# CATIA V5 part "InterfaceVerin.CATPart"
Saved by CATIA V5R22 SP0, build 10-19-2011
Part number: InterfaceVerin
Material "Vert": density 7860 kg/m3, Young's modulus 2e+11 Pa, Poisson ratio 0.266
Bounding box of the stored display mesh (mm): x 0 to 114.936, y -17 to 72, z 0 to 43
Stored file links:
  Z:\S9A\PER\CAO_Projet_ZG4\Cadre\Chariot_Y\Prehenseur\InterfaceVerin.CATPart
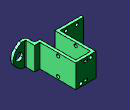
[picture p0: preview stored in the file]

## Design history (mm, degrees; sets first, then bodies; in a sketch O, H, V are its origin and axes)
Body1 (main body), material "Vert"
  Sketch1 on xy-plane, origin (0, 0, 0), H (1, 0, 0), V (0, 1, 0)
    line L1 (0, 0) -> (49, 0)
    line L2 (87, 0) -> (87, -11)
    point P1 (87, -17)
    line L3 (93, -17) -> (117, -17)
    point P2 (117, -17)
    point P3 (87, 0)
    point P4 (87, 0)
    arc A1 centre (93, -11) radius 6 from (93, -17) to (87, -11) cw
    line L4 (49, 0) -> (49, 67)
    line L5 (49, 67) -> (77, 67)
    line L6 (77, 67) -> (77, 0)
    line L7 (77, 0) -> (87, 0)
    distance P1 P2 = 30
    radius A1 = 6
    length L6 = 67
    length L5 = 28
    length L7 = 10
    length L2 = 11
    length L1 = 49
    horizontal: L1 H, L3 H, L5 H, L7 H
    vertical: L2 V, L4 V, L6 V
    coincidence: L3 P1, L2 P1, P4 P3, L1 L7
    tangency: A1 L3, A1 L2
  Pad1: profile Sketch1, direction (0, 0, 1), length 43, thin wall 5
  Sketch2 on face of Pad1, origin (98.7676, -12, 26.3573), H (1, 0, 0), V (0, 0, -1)
    point P1 (4.7324, 4.8573)
    reference projected line E1 (-5.7676, 26.3573) -> (18.2324, 26.3573) from edge [face of Pad1 | start face of Pad1]
    reference projected line E2 through (-5.7676, 0) direction (0, -1) from axis of face of Pad1
    distance P1 E1 = 21.5
    distance P1 E2 = 10.5
  Hole1: placed by Sketch2, at (103.5, -12, 21.5) direction (0, -1, 0), diameter 14, depth 21
  Sketch3 on face of Pad1, origin (0, 72, 0), H (-1, 0, 0), V (0, 0, 1)
    circle A1 centre (-72, 5) radius 3
    point P1 (-72, 5)
    circle A2 centre (-54, 38) radius 3
    point P2 (-54, 38)
    reference projected line E1 (-82, 0) -> (-44, 0) from edge [start face of Pad1 | face of Pad1]
    reference projected line E2 (-82, 43) -> (-44, 43) from edge [face of Pad1 | end face of Pad1]
    reference projected line E3 (-44, 0) -> (-44, 43) from edge [face of Pad1 | face of Pad1]
    line L1 (-66, 8) -> (-60, 8)
    line L2 (-60, 8) -> (-60, 4)
    line L3 (-60, 4) -> (-66, 4)
    line L4 (-66, 4) -> (-66, 8)
    line L5 (-66, 39) -> (-60, 39)
    line L6 (-60, 39) -> (-60, 35)
    line L7 (-60, 35) -> (-66, 35)
    line L8 (-66, 35) -> (-66, 39)
    reference projected line E4 (-82, 0) -> (-82, 43) from edge [face of Pad1 | face of Pad1]
    reference projected line E5 (-44, 0) -> (-44, 43) from edge [face of Pad1 | face of Pad1]
    reference projected line E6 (-82, 0) -> (-82, 43) from edge [face of Pad1 | face of Pad1]
    reference projected line E7 (-44, 0) -> (-44, 43) from edge [face of Pad1 | face of Pad1]
    reference projected line E8 (-82, 0) -> (-82, 43) from edge [face of Pad1 | face of Pad1]
    reference projected line E9 (-82, 43) -> (-44, 43) from edge [face of Pad1 | end face of Pad1]
    reference projected line E10 (-82, 0) -> (-44, 0) from edge [start face of Pad1 | face of Pad1]
    reference projected line E11 (-82, 0) -> (-82, 43) from edge [face of Pad1 | face of Pad1]
    reference projected line E12 (-82, 0) -> (-82, 43) from edge [face of Pad1 | face of Pad1]
    radius A2 = 3
    radius A1 = 3
    distance P1 E1 = 5
    distance P2 E2 = 5
    distance P2 E3 = 10
    length L5 = 6
    length L6 = 4
    length L3 = 6
    length L2 = 4
    distance L8 E4 = 16
    distance E5 E6 = 38 (reference)
    distance E7 E8 = 38 (reference)
    distance L5 E9 = 4
    distance L3 E10 = 4
    distance L4 E11 = 16
    distance P1 E12 = 10
    horizontal: L1 H, L3 H, L5 H, L7 H
    vertical: L2 V, L4 V, L6 V, L8 V
  Pocket1: profile Sketch3, direction (0, -1, 0), through (limit type 3)
  Sketch4 on face of Pad1, origin (0, 5, 0), H (-1, 0, 0), V (0, 0, 1)
    circle A1 centre (-33, 37) radius 3
    point P1 (-33, 37)
    circle A2 centre (-13, 37) radius 3
    point P2 (-13, 37)
    circle A3 centre (-33, 7) radius 3
    point P3 (-33, 7)
    circle A4 centre (-13, 7) radius 3
    point P4 (-13, 7)
    reference projected line E1 (0, 0) -> (-44, 0) from edge [face of Pad1 | start face of Pad1]
    reference projected line E2 (0, 43) -> (-44, 43) from edge [end face of Pad1 | face of Pad1]
    reference projected line E3 (0, 0) -> (-44, 0) from edge [face of Pad1 | start face of Pad1]
    reference projected line E4 (0, 0) -> (-44, 0) from edge [face of Pad1 | start face of Pad1]
    reference projected line E5 (-44, 0) -> (-44, 43) from edge [face of Pad1 | face of Pad1]
    reference projected line E6 (-44, 0) -> (-44, 43) from edge [face of Pad1 | face of Pad1]
    radius A1 = 3
    radius A2 = 3
    radius A3 = 3
    radius A4 = 3
    distance P2 P4 = 30
    distance P3 P1 = 30
    distance P3 E1 = 7
    distance E2 E3 = 43 (reference)
    distance P2 P1 = 20
    distance P4 P3 = 20
    distance P4 E4 = 7
    distance P3 E5 = 11
    distance P1 E6 = 11
  Pocket2: profile Sketch4, direction (0, -1, 0), through (limit type 3)
  Sketch5 on face of Pad1, origin (0, -12, 0), H (-1, 0, 0), V (0, 0, 1)
    line L1 (-100, 43) -> (-150, 43)
    point P1 (-100, 43)
    point P2 (-150, 43)
    line L2 (-150, 43) -> (-150, 0)
    line L3 (-150, 0) -> (-100, 0)
    point P4 (-100, 0)
    line L4 (-100, 0) -> (-108.3732, 7.201)
    point P5 (-125, 21.5)
    line L5 (-100, 43) -> (-108.3732, 35.799)
    reference projected line E1 (-93, 43) -> (-117, 43) from edge [end face of Pad1 | face of Pad1]
    reference projected line E2 (-93, 0) -> (-117, 0) from edge [face of Pad1 | start face of Pad1]
    reference projected line E3 (-93, 0) -> (-93, 43) from edge [face of Pad1 | face of Pad1]
    reference projected line E4 (-93, 0) -> (-93, 43) from edge [face of Pad1 | face of Pad1]
    arc A1 centre (-96.0761, 21.5) radius 18.8595 from (-108.3732, 35.799) to (-108.3732, 7.201) ccw
    reference projected line E5 (-93, 0) -> (-93, 43) from edge [face of Pad1 | face of Pad1]
    reference projected circle E6 centre (-103.5, 21.5) radius 7 from edge [face of Hole1 | face of Pad1]
    distance P5 L1 = 21.5
    distance E3 P1 = 7
    distance E4 P4 = 7
    radius A1 = 18.8595
    distance E5 E6 = 3.5 (reference)
    horizontal: L1 H, L3 H
    vertical: L2 V
    coincidence: L4 P2, E1 L1, E2 L3, L5 P5, L4 P5
    tangency: A1 L5, A1 L4
  Pocket3: profile Sketch5, direction (0, -1, 0), through (limit type 3), offset 10
  Fillet1: radius 4, on edge [face of Pad1 | face of Pad1]
  Sketch6 on face of Pad1, origin (82, 0, 0), H (0, 1, 0), V (0, 0, 1)
    circle A1 centre (39, 38) radius 3
    point P1 (39, 38)
    circle A2 centre (39, 5) radius 3
    point P2 (39, 5)
    reference projected line E1 (72, 0) -> (5, 0) from edge [face of Pad1 | start face of Pad1]
    reference projected line E2 (72, 43) -> (5, 43) from edge [end face of Pad1 | face of Pad1]
    reference projected line E3 (72, 0) -> (72, 43) from edge [face of Pad1 | face of Pad1]
    reference projected line E4 (72, 0) -> (72, 43) from edge [face of Pad1 | face of Pad1]
    radius A2 = 3
    radius A1 = 3
    distance P2 E1 = 5
    distance P1 E2 = 5
    distance E3 P1 = 33
    distance E4 P2 = 33
  Pocket4: profile Sketch6, direction (-1, 0, 0), through (limit type 3), offset 100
